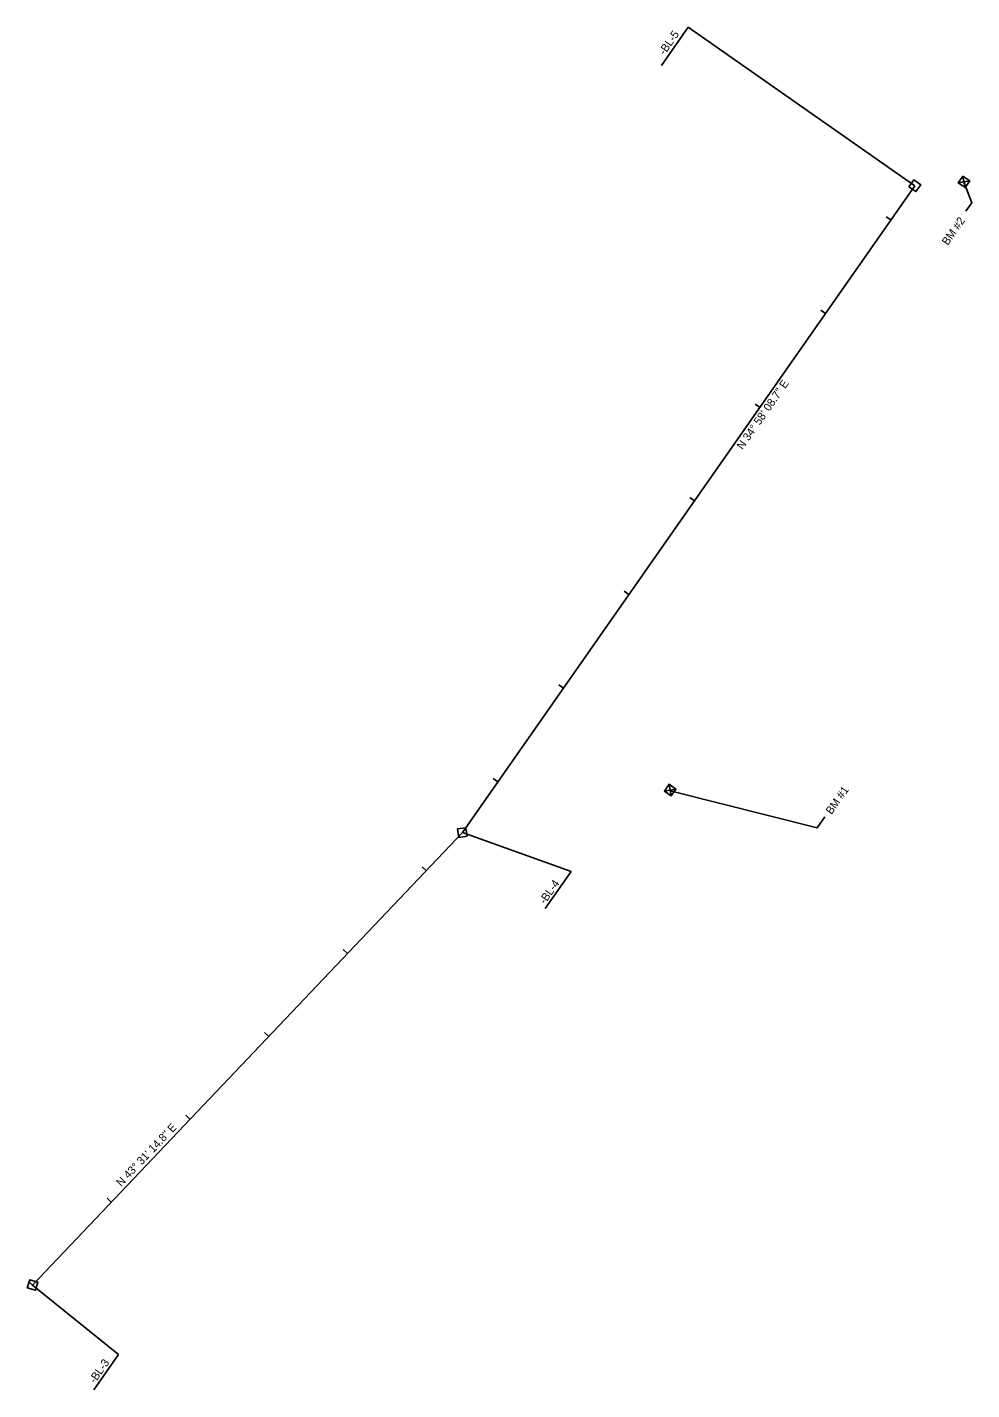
# Model space of a CAD drawing. Extents: x 1730872 to 1733524, y 884534 to 887085.
# Drawn here: x 1731818 to 1732644, y 885019 to 886211 of the extents above; entities that cross this region are included whole.
import ezdxf

# ---------------------------------------------------------------- set-up
doc = ezdxf.new("R2010")
doc.units = 0
for name, color, linetype in [('Exist Horizontal Alignment', 7, 'Continuous'), ('Exist Roads EOP Other Text', 7, 'Continuous'), ('Exist Utilities Power Pole Text Tag Number', 7, 'Continuous'), ('Prop EOT', 7, 'Continuous'), ('Prop Horizontal Alignment', 7, 'Continuous'), ('Prop Horizontal Alignment Direction Label', 7, 'Continuous'), ('Scratch_Level_1', 7, 'Continuous')]:
    doc.layers.add(name, color=color, linetype=linetype)

msp = doc.modelspace()

# ---------------------------------------------------------------- linework, layer by layer
at = {"layer": 'Exist Horizontal Alignment'}
for p, q in [((1732372.9, 886178), (1732396.2, 886211.3)), ((1732594.5, 886072.6), (1732396.2, 886211.3)), ((1732198.8, 885506.8), (1732293.9, 885472.6)), ((1732271.3, 885440.4), (1732293.9, 885472.6)), ((1731822.8, 885110.9), (1731898.1, 885050.2)), ((1731898.1, 885050.2), (1731876.5, 885019.3))]:
    msp.add_line(p, q, dxfattribs=at)
at = {"layer": 'Exist Roads EOP Other Text'}
for p, q in [((1732637.5, 886076), (1732637.5, 886076)), ((1732380.5, 885544), (1732380.5, 885544))]:
    msp.add_line(p, q, dxfattribs=at)
for points in [[(1732632.5, 886075.1), (1732636.6, 886081), (1732642.5, 886076.9), (1732638.4, 886071)], [(1732375.5, 885543.1), (1732379.6, 885549), (1732385.5, 885544.8), (1732381.4, 885539)]]:
    msp.add_lwpolyline(points, close=True, dxfattribs=at)
for points in [[(1732636.6, 886081), (1732638.4, 886071), (1732637.5, 886076), (1732642.5, 886076.9), (1732632.5, 886075.1)], [(1732637.5, 886076), (1732636.6, 886081), (1732632.5, 886075.1), (1732637.5, 886076)], [(1732637.5, 886076), (1732638.4, 886071), (1732642.5, 886076.9), (1732637.5, 886076)], [(1732379.6, 885549), (1732381.4, 885539), (1732380.5, 885544), (1732385.5, 885544.8), (1732375.5, 885543.1)], [(1732380.5, 885544), (1732379.6, 885549), (1732375.5, 885543.1), (1732380.5, 885544)], [(1732380.5, 885544), (1732381.4, 885539), (1732385.5, 885544.8), (1732380.5, 885544)]]:
    msp.add_lwpolyline(points, dxfattribs=at)
at = {"layer": 'Exist Utilities Power Pole Text Tag Number'}
for points in [[(1732639.1, 886050.3), (1732644.3, 886057.6), (1732637.4, 886076)], [(1732380.5, 885543.3), (1732509, 885510.8), (1732515.8, 885520.6)]]:
    msp.add_lwpolyline(points, dxfattribs=at)
at = {"layer": 'Prop EOT'}
for p, q in [((1732573.6, 886042.8), (1732569.5, 886045.6)), ((1732516.3, 885960.8), (1732512.2, 885963.7)), ((1732459, 885878.9), (1732454.9, 885881.7)), ((1732401.7, 885796.9), (1732397.6, 885799.8)), ((1732344.4, 885715), (1732340.3, 885717.9)), ((1732287.1, 885633), (1732283, 885635.9)), ((1732229.7, 885551.1), (1732225.6, 885554)), ((1732167.1, 885473.5), (1732163.5, 885476.9)), ((1732098.3, 885401), (1732094.6, 885404.4)), ((1732029.4, 885328.5), (1732025.8, 885331.9)), ((1731960.5, 885255.9), (1731956.9, 885259.4)), ((1731891.7, 885183.4), (1731888.1, 885186.9)), ((1731822.8, 885110.9), (1731819.2, 885114.4))]:
    msp.add_line(p, q, dxfattribs=at)
at = {"layer": 'Prop Horizontal Alignment'}
for p, q in [((1732198.8, 885506.8), (1732594.5, 886072.6)), ((1731822.8, 885110.9), (1732198.8, 885506.8))]:
    msp.add_line(p, q, dxfattribs=at)
at = {"layer": 'Scratch_Level_1'}
for p, q in [((1732594.5, 886072.6), (1732594.5, 886072.6)), ((1732198.8, 885506.8), (1732198.8, 885506.8)), ((1731822.8, 885110.9), (1731822.8, 885110.9))]:
    msp.add_line(p, q, dxfattribs=at)
for points in [[(1732589.4, 886071.7), (1732593.6, 886077.8), (1732599.7, 886073.6), (1732595.5, 886067.5)], [(1732203, 885503.7), (1732195.6, 885502.6), (1732194.5, 885509.9), (1732201.8, 885511)], [(1731818.2, 885108.5), (1731820.4, 885115.6), (1731827.5, 885113.4), (1731825.3, 885106.3)]]:
    msp.add_lwpolyline(points, close=True, dxfattribs=at)

# ---------------------------------------------------------------- texts
at = {"layer": 'Exist Horizontal Alignment'}
for s, p in [('-BL-5 ', (1732375.6, 886186.5)), ('-BL-4 ', (1732271, 885443.6)), ('-BL-3 ', (1731877.3, 885024.3))]:
    msp.add_text(s, height=7, rotation=55.0251, dxfattribs=at).set_placement(p)
at = {"layer": 'Exist Utilities Power Pole Text Tag Number'}
for s, rotation, p in [('BM #2', 55.0444, (1732623.3, 886020)), ('BM #1', 55.2503, (1732521.7, 885522))]:
    msp.add_text(s, height=7, rotation=rotation, dxfattribs=at).set_placement(p)
at = {"layer": 'Prop Horizontal Alignment Direction Label'}
for s, rotation, p in [('N 34%%d 58\' 08.7" E', 55.0309, (1732443.8, 885841.3)), ('N 43%%d 31\' 14.8" E', 46.4792, (1731900.3, 885196.6))]:
    msp.add_text(s, height=7, rotation=rotation, dxfattribs=at).set_placement(p)

doc.saveas('drawing.dxf')
